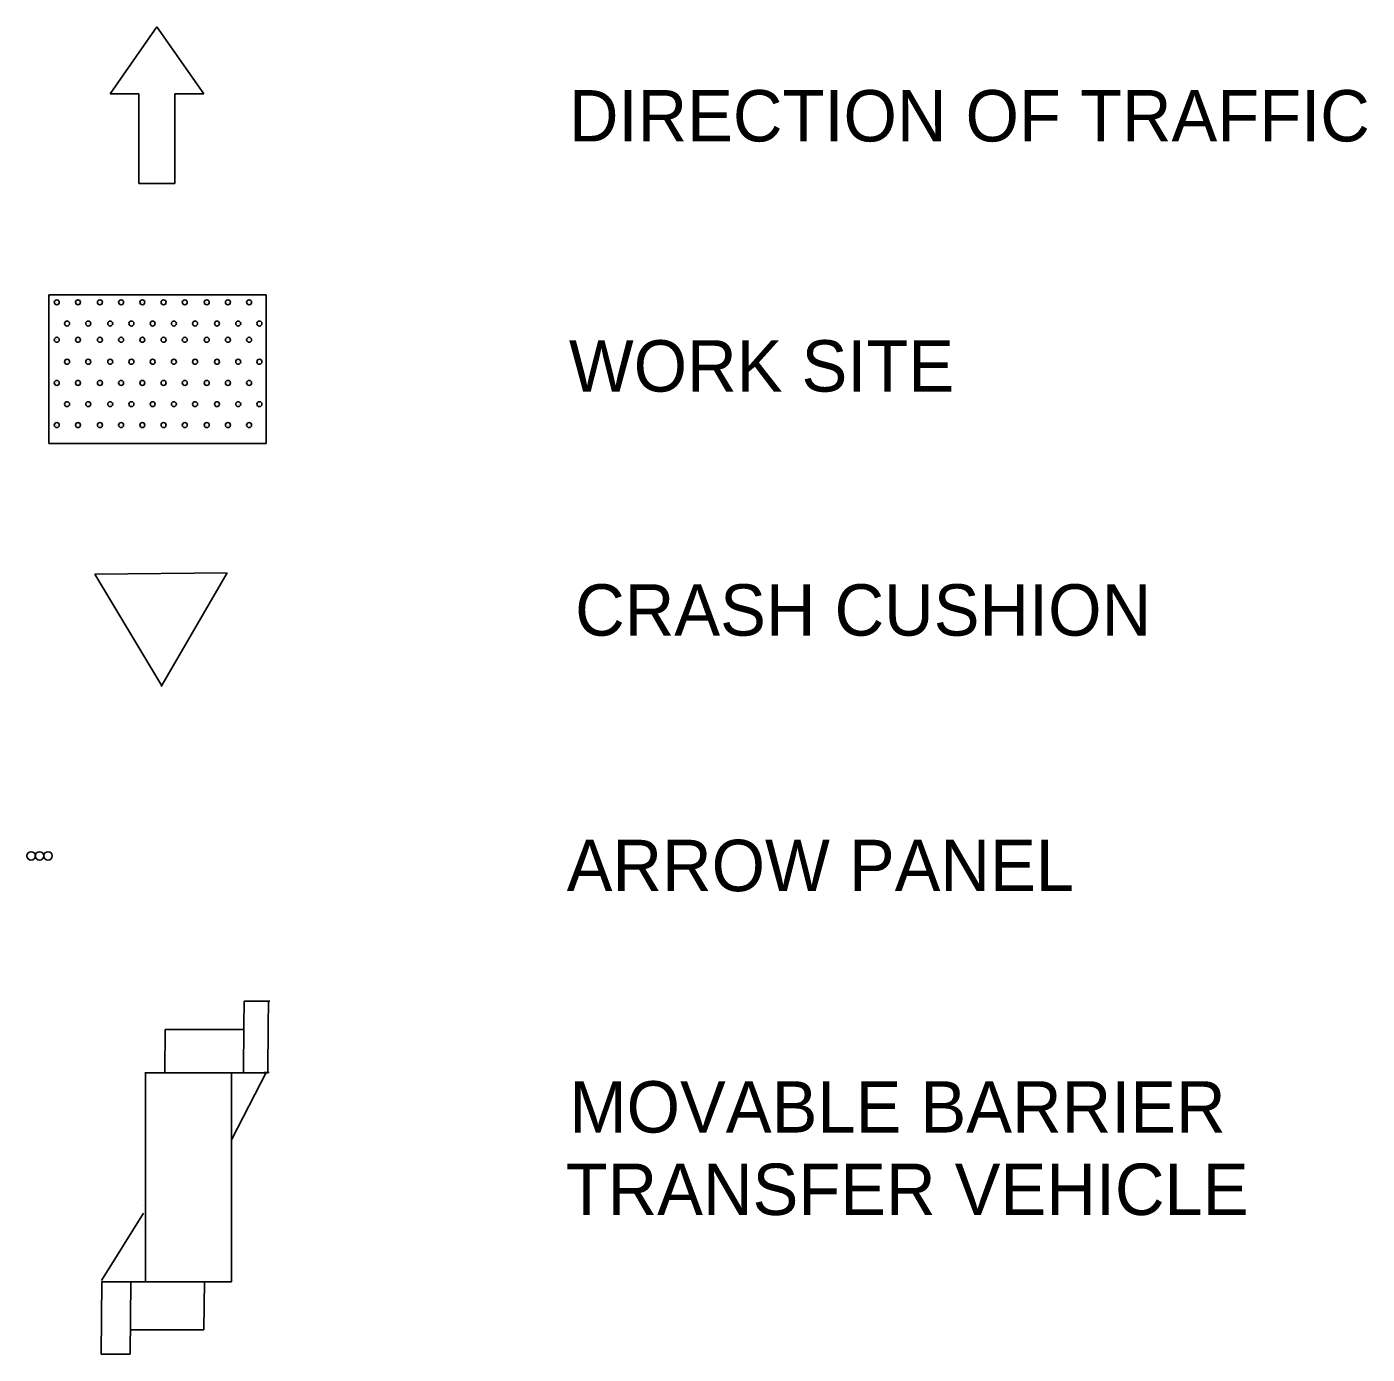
# Model space of a CAD drawing. Extents: x 54531.5 to 54538.4, y 53883.4 to 53893.4.
# Drawn here: x 54531.615 to 54533.182, y 53887.154 to 53888.705 of the extents above; entities that cross this region are included whole.
import ezdxf

# ---------------------------------------------------------------- set-up
doc = ezdxf.new("R2010")
doc.units = 0
for name, color, linetype in [('DETL-LINE', 7, 'Continuous'), ('DETL-NOTE', 7, 'Continuous'), ('USER-BORD', 7, 'Continuous')]:
    doc.layers.add(name, color=color, linetype=linetype)

# ---------------------------------------------------------------- blocks, each defined once
blk = doc.blocks.new('PANEL0')
at = {"layer": 'USER-BORD'}
for centre in [(0.0309, -0.0012), (0.0928, -0.0012), (0.1546, -0.0012)]:
    blk.add_circle(centre, 0.0312, dxfattribs=at)
blk = doc.blocks.new('DIR2')
at = {"layer": 'USER-BORD'}
for p, q in [((0, 0.012), (-0.342, -0.477)), ((0, 0.012), (0.342, -0.477)), ((-0.342, -0.477), (-0.132, -0.477)), ((-0.132, -1.133), (-0.132, -0.477)), ((0.342, -0.477), (0.132, -0.477)), ((0.132, -1.133), (0.132, -0.477)), ((-0.011, -1.133), (-0.132, -1.133)), ((-0.011, -1.133), (0.011, -1.133)), ((0.011, -1.133), (0.132, -1.133))]:
    blk.add_line(p, q, dxfattribs=at)

msp = doc.modelspace()

# ---------------------------------------------------------------- linework, layer by layer
at = {"layer": 'DETL-LINE'}
for p, q in [((54531.6408, 53888.2178), (54531.6408, 53888.3918)), ((54531.8948, 53888.3918), (54531.6408, 53888.3918)), ((54531.8948, 53888.3918), (54531.6408, 53888.3918)), ((54531.8948, 53888.3918), (54531.6408, 53888.3918)), ((54531.8948, 53888.3918), (54531.6408, 53888.3918)), ((54531.6409, 53888.2178), (54531.6409, 53888.3918)), ((54531.6494, 53888.3829), (54531.6494, 53888.3829)), ((54531.6502, 53888.3829), (54531.6502, 53888.3829)), ((54531.675, 53888.3829), (54531.675, 53888.3829)), ((54531.675, 53888.3829), (54531.675, 53888.3829)), ((54531.6998, 53888.3829), (54531.6998, 53888.3829)), ((54531.7006, 53888.3829), (54531.7006, 53888.3829)), ((54531.7246, 53888.3829), (54531.7246, 53888.3829)), ((54531.7254, 53888.3829), (54531.7254, 53888.3829)), ((54531.7494, 53888.3829), (54531.7494, 53888.3829)), ((54531.7502, 53888.3829), (54531.7502, 53888.3829)), ((54531.775, 53888.3829), (54531.775, 53888.3829)), ((54531.775, 53888.3829), (54531.775, 53888.3829)), ((54531.7998, 53888.3829), (54531.7998, 53888.3829)), ((54531.7998, 53888.3829), (54531.7998, 53888.3829)), ((54531.8246, 53888.3829), (54531.8246, 53888.3829)), ((54531.8254, 53888.3829), (54531.8254, 53888.3829)), ((54531.8494, 53888.3829), (54531.8494, 53888.3829)), ((54531.8502, 53888.3829), (54531.8502, 53888.3829)), ((54531.875, 53888.3829), (54531.875, 53888.3829)), ((54531.875, 53888.3829), (54531.875, 53888.3829)), ((54531.8948, 53888.2178), (54531.8948, 53888.3918)), ((54531.8948, 53888.2178), (54531.8948, 53888.3918)), ((54531.8948, 53888.2178), (54531.8948, 53888.3918)), ((54531.8948, 53888.2178), (54531.8948, 53888.3918)), ((54531.6622, 53888.3581), (54531.6622, 53888.3581)), ((54531.6622, 53888.3581), (54531.6622, 53888.3581)), ((54531.687, 53888.3581), (54531.687, 53888.3581)), ((54531.687, 53888.3581), (54531.687, 53888.3581)), ((54531.7126, 53888.3581), (54531.7126, 53888.3581)), ((54531.7126, 53888.3581), (54531.7126, 53888.3581)), ((54531.7374, 53888.3581), (54531.7374, 53888.3581)), ((54531.7374, 53888.3581), (54531.7374, 53888.3581)), ((54531.7622, 53888.3581), (54531.7622, 53888.3581)), ((54531.7622, 53888.3581), (54531.7622, 53888.3581)), ((54531.787, 53888.3581), (54531.787, 53888.3581)), ((54531.787, 53888.3581), (54531.787, 53888.3581)), ((54531.8118, 53888.3581), (54531.8118, 53888.3581)), ((54531.8118, 53888.3581), (54531.8118, 53888.3581)), ((54531.8374, 53888.3581), (54531.8374, 53888.3581)), ((54531.8374, 53888.3581), (54531.8374, 53888.3581)), ((54531.8622, 53888.3581), (54531.8622, 53888.3581)), ((54531.8622, 53888.3581), (54531.8622, 53888.3581)), ((54531.887, 53888.3581), (54531.887, 53888.3581)), ((54531.887, 53888.3581), (54531.887, 53888.3581)), ((54531.6494, 53888.3391), (54531.6494, 53888.3391)), ((54531.6502, 53888.3391), (54531.6502, 53888.3391)), ((54531.675, 53888.3391), (54531.675, 53888.3391)), ((54531.675, 53888.3391), (54531.675, 53888.3391)), ((54531.6998, 53888.3391), (54531.6998, 53888.3391)), ((54531.7006, 53888.3391), (54531.7006, 53888.3391)), ((54531.7246, 53888.3391), (54531.7246, 53888.3391)), ((54531.7254, 53888.3391), (54531.7254, 53888.3391)), ((54531.7494, 53888.3391), (54531.7494, 53888.3391)), ((54531.7502, 53888.3391), (54531.7502, 53888.3391)), ((54531.775, 53888.3391), (54531.775, 53888.3391)), ((54531.775, 53888.3391), (54531.775, 53888.3391)), ((54531.7998, 53888.3391), (54531.7998, 53888.3391)), ((54531.7998, 53888.3391), (54531.7998, 53888.3391)), ((54531.8246, 53888.3391), (54531.8246, 53888.3391)), ((54531.8254, 53888.3391), (54531.8254, 53888.3391)), ((54531.8494, 53888.3391), (54531.8494, 53888.3391)), ((54531.8502, 53888.3391), (54531.8502, 53888.3391)), ((54531.875, 53888.3391), (54531.875, 53888.3391)), ((54531.875, 53888.3391), (54531.875, 53888.3391)), ((54531.6622, 53888.3135), (54531.6622, 53888.3135)), ((54531.687, 53888.3135), (54531.687, 53888.3135)), ((54531.7126, 53888.3135), (54531.7126, 53888.3135)), ((54531.7374, 53888.3135), (54531.7374, 53888.3135)), ((54531.7622, 53888.3135), (54531.7622, 53888.3135)), ((54531.787, 53888.3135), (54531.787, 53888.3135)), ((54531.8118, 53888.3135), (54531.8118, 53888.3135)), ((54531.8374, 53888.3135), (54531.8374, 53888.3135)), ((54531.8622, 53888.3135), (54531.8622, 53888.3135)), ((54531.887, 53888.3135), (54531.887, 53888.3135)), ((54531.6494, 53888.2887), (54531.6494, 53888.2887)), ((54531.6502, 53888.2887), (54531.6502, 53888.2887)), ((54531.675, 53888.2887), (54531.675, 53888.2887)), ((54531.675, 53888.2887), (54531.675, 53888.2887)), ((54531.6998, 53888.2887), (54531.6998, 53888.2887)), ((54531.7006, 53888.2887), (54531.7006, 53888.2887)), ((54531.7246, 53888.2887), (54531.7246, 53888.2887)), ((54531.7254, 53888.2887), (54531.7254, 53888.2887)), ((54531.7494, 53888.2887), (54531.7494, 53888.2887)), ((54531.7502, 53888.2887), (54531.7502, 53888.2887)), ((54531.775, 53888.2887), (54531.775, 53888.2887)), ((54531.775, 53888.2887), (54531.775, 53888.2887)), ((54531.7998, 53888.2887), (54531.7998, 53888.2887)), ((54531.7998, 53888.2887), (54531.7998, 53888.2887)), ((54531.8246, 53888.2887), (54531.8246, 53888.2887)), ((54531.8254, 53888.2887), (54531.8254, 53888.2887)), ((54531.8494, 53888.2887), (54531.8494, 53888.2887)), ((54531.8502, 53888.2887), (54531.8502, 53888.2887)), ((54531.875, 53888.2887), (54531.875, 53888.2887)), ((54531.875, 53888.2887), (54531.875, 53888.2887)), ((54531.6622, 53888.2639), (54531.6622, 53888.2639)), ((54531.6622, 53888.2639), (54531.6622, 53888.2639)), ((54531.687, 53888.2639), (54531.687, 53888.2639)), ((54531.687, 53888.2639), (54531.687, 53888.2639)), ((54531.7126, 53888.2639), (54531.7126, 53888.2639)), ((54531.7126, 53888.2639), (54531.7126, 53888.2639)), ((54531.7374, 53888.2639), (54531.7374, 53888.2639)), ((54531.7374, 53888.2639), (54531.7374, 53888.2639)), ((54531.7622, 53888.2639), (54531.7622, 53888.2639)), ((54531.7622, 53888.2639), (54531.7622, 53888.2639)), ((54531.787, 53888.2639), (54531.787, 53888.2639)), ((54531.787, 53888.2639), (54531.787, 53888.2639)), ((54531.8118, 53888.2639), (54531.8118, 53888.2639)), ((54531.8118, 53888.2639), (54531.8118, 53888.2639)), ((54531.8374, 53888.2639), (54531.8374, 53888.2639)), ((54531.8374, 53888.2639), (54531.8374, 53888.2639)), ((54531.8622, 53888.2639), (54531.8622, 53888.2639)), ((54531.8622, 53888.2639), (54531.8622, 53888.2639)), ((54531.887, 53888.2639), (54531.887, 53888.2639)), ((54531.887, 53888.2639), (54531.887, 53888.2639)), ((54531.6494, 53888.2395), (54531.6494, 53888.2395)), ((54531.6502, 53888.2395), (54531.6502, 53888.2395)), ((54531.675, 53888.2395), (54531.675, 53888.2395)), ((54531.675, 53888.2395), (54531.675, 53888.2395)), ((54531.6998, 53888.2395), (54531.6998, 53888.2395)), ((54531.7006, 53888.2395), (54531.7006, 53888.2395)), ((54531.7246, 53888.2395), (54531.7246, 53888.2395)), ((54531.7254, 53888.2395), (54531.7254, 53888.2395)), ((54531.7494, 53888.2395), (54531.7494, 53888.2395)), ((54531.7502, 53888.2395), (54531.7502, 53888.2395)), ((54531.775, 53888.2395), (54531.775, 53888.2395)), ((54531.775, 53888.2395), (54531.775, 53888.2395)), ((54531.7998, 53888.2395), (54531.7998, 53888.2395)), ((54531.7998, 53888.2395), (54531.7998, 53888.2395)), ((54531.8246, 53888.2395), (54531.8246, 53888.2395)), ((54531.8254, 53888.2395), (54531.8254, 53888.2395)), ((54531.8494, 53888.2395), (54531.8494, 53888.2395)), ((54531.8502, 53888.2395), (54531.8502, 53888.2395)), ((54531.875, 53888.2395), (54531.875, 53888.2395)), ((54531.875, 53888.2395), (54531.875, 53888.2395)), ((54531.6408, 53888.2178), (54531.8948, 53888.2178)), ((54531.6945, 53888.0653), (54531.8493, 53888.0668)), ((54531.6945, 53888.0653), (54531.7728, 53887.9347)), ((54531.7722, 53887.9339), (54531.8493, 53888.0668)), ((54531.8687, 53887.5375), (54531.8689, 53887.5665)), ((54531.8689, 53887.5665), (54531.899, 53887.5663)), ((54531.8972, 53887.5375), (54531.8975, 53887.5665)), ((54531.7762, 53887.4835), (54531.7767, 53887.5335)), ((54531.7767, 53887.5335), (54531.8687, 53887.5335)), ((54531.8687, 53887.5375), (54531.8682, 53887.4837)), ((54531.8972, 53887.5375), (54531.8968, 53887.4837)), ((54531.7538, 53887.2388), (54531.7538, 53887.4835)), ((54531.7538, 53887.4827), (54531.8967, 53887.4827)), ((54531.8544, 53887.4835), (54531.8544, 53887.2388)), ((54531.8948, 53887.4831), (54531.8548, 53887.4054)), ((54531.8983, 53887.4831), (54531.8923, 53887.4831)), ((54531.7515, 53887.3279), (54531.7515, 53887.3279)), ((54531.7022, 53887.2403), (54531.7515, 53887.3189)), ((54531.702, 53887.1541), (54531.7027, 53887.2391)), ((54531.7027, 53887.2388), (54531.8544, 53887.2388)), ((54531.7359, 53887.1541), (54531.7366, 53887.2388)), ((54531.8226, 53887.2393), (54531.8221, 53887.1827)), ((54531.7361, 53887.1827), (54531.8221, 53887.1827)), ((54531.702, 53887.1541), (54531.7359, 53887.1541))]:
    msp.add_line(p, q, dxfattribs=at)
for centre in [(54531.6501, 53888.3829), (54531.6749, 53888.3829), (54531.7005, 53888.3829), (54531.7253, 53888.3829), (54531.7501, 53888.3829), (54531.7749, 53888.3829), (54531.7997, 53888.3829), (54531.8253, 53888.3829), (54531.8501, 53888.3829), (54531.8749, 53888.3829), (54531.6621, 53888.3581), (54531.6869, 53888.3581), (54531.7125, 53888.3581), (54531.7373, 53888.3581), (54531.7621, 53888.3581), (54531.7869, 53888.3581), (54531.8117, 53888.3581), (54531.8373, 53888.3581), (54531.8621, 53888.3581), (54531.8869, 53888.3581), (54531.6501, 53888.3391), (54531.6749, 53888.3391), (54531.7005, 53888.3391), (54531.7253, 53888.3391), (54531.7501, 53888.3391), (54531.7749, 53888.3391), (54531.7997, 53888.3391), (54531.8253, 53888.3391), (54531.8501, 53888.3391), (54531.8749, 53888.3391), (54531.6621, 53888.3135), (54531.6869, 53888.3135), (54531.7125, 53888.3135), (54531.7373, 53888.3135), (54531.7621, 53888.3135), (54531.7869, 53888.3135), (54531.8117, 53888.3135), (54531.8373, 53888.3135), (54531.8621, 53888.3135), (54531.8869, 53888.3135), (54531.6501, 53888.2887), (54531.6749, 53888.2887), (54531.7005, 53888.2887), (54531.7253, 53888.2887), (54531.7501, 53888.2887), (54531.7749, 53888.2887), (54531.7997, 53888.2887), (54531.8253, 53888.2887), (54531.8501, 53888.2887), (54531.8749, 53888.2887), (54531.6621, 53888.2639), (54531.6869, 53888.2639), (54531.7125, 53888.2639), (54531.7373, 53888.2639), (54531.7621, 53888.2639), (54531.7869, 53888.2639), (54531.8117, 53888.2639), (54531.8373, 53888.2639), (54531.8621, 53888.2639), (54531.8869, 53888.2639), (54531.6501, 53888.2395), (54531.6749, 53888.2395), (54531.7005, 53888.2395), (54531.7253, 53888.2395), (54531.7501, 53888.2395), (54531.7749, 53888.2395), (54531.7997, 53888.2395), (54531.8253, 53888.2395), (54531.8501, 53888.2395), (54531.8749, 53888.2395)]:
    msp.add_circle(centre, 0.00291, dxfattribs=at)

# ---------------------------------------------------------------- block references
at = {"layer": 'DETL-LINE', "xscale": 0.16, "yscale": 0.16}
for name, p in [('DIR2', (54531.7671, 53888.7028)), ('PANEL0', (54531.6151, 53887.7363))]:
    msp.add_blockref(name, p, dxfattribs=at)

# ---------------------------------------------------------------- texts
at = {"layer": 'DETL-NOTE'}
for s, p in [('DIRECTION OF TRAFFIC', (54532.2486, 53888.5708)), ('WORK SITE', (54532.2486, 53888.2786)), ('CRASH CUSHION', (54532.2559, 53887.9935)), ('ARROW PANEL', (54532.246, 53887.695)), ('MOVABLE BARRIER', (54532.2492, 53887.413)), ('TRANSFER VEHICLE', (54532.2448, 53887.3167))]:
    msp.add_text(s, height=0.06, dxfattribs=at).set_placement(p)

doc.saveas('drawing.dxf')
